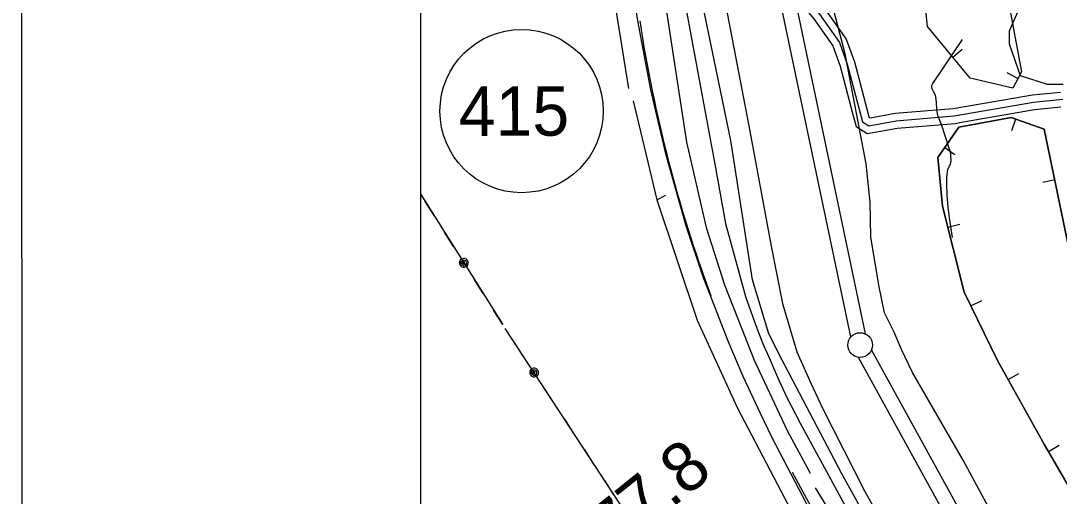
# Model space of a CAD drawing. Extents: x 3279314 to 3317160, y 734079 to 759431.
# Drawn here: x 3282648 to 3284746, y 754513 to 755474 of the extents above; entities that cross this region are included whole.
import ezdxf

# ---------------------------------------------------------------- set-up
doc = ezdxf.new("R2010")
doc.units = 0
for name, color, linetype in [('V-ANNO-SYMB', 7, 'Continuous'), ('V-BORW-LINE', 7, 'Continuous'), ('V-GRID-FRAM', 7, 'Continuous'), ('V-LEVE-TOET', 7, 'Continuous'), ('V-RAIL-TRAK', 7, 'Continuous'), ('V-ROAD-CNTR', 7, 'Continuous'), ('V-ROAD-IDEN', 7, 'Continuous'), ('V-SITE-VEGE', 7, 'Continuous'), ('V-SURV-IDEN', 7, 'Continuous'), ('V-SURV-LINE', 7, 'Continuous'), ('V-TOPO-SHOR', 7, 'Continuous'), ('V-UTIL-LINE', 7, 'Continuous')]:
    doc.layers.add(name, color=color, linetype=linetype)

msp = doc.modelspace()

# ---------------------------------------------------------------- linework, layer by layer
at = {"layer": 'V-ANNO-SYMB'}
msp.add_lwpolyline([(3282659.5, 735288.8), (3315742.7, 735305.7), (3315731, 758222.2), (3282647.8, 758205.4), (3282659.5, 735288.8)], dxfattribs=at)
at = {"layer": 'V-BORW-LINE'}
for p, q in [((3284530.4, 755400.2), (3284549.8, 755416)), ((3284662.3, 755356.9), (3284640.2, 755368.5)), ((3284657, 755274.9), (3284648.9, 755251.3)), ((3284514.4, 755217.2), (3284535, 755203.1)), ((3284736.7, 755152.1), (3284712.2, 755147)), ((3284520.5, 755056.6), (3284544.7, 755062.7)), ((3284566.9, 754897.2), (3284589.4, 754908.2)), ((3284642.3, 754748.7), (3284664.2, 754760.9)), ((3284723.6, 754603.3), (3284745.2, 754615.8))]:
    msp.add_line(p, q, dxfattribs=at)
for points in [[(3284443.5, 756381.2), (3284529.5, 756266.7), (3284588.4, 755977.5), (3284641.4, 755699.9), (3284641.7, 755519), (3284669.4, 755370.4), (3284651.9, 755337), (3284565.4, 755357.5), (3284479.7, 755462.1), (3284467.3, 755583.5), (3284485.3, 755733.9), (3284482.4, 755883.7), (3284433.7, 756025.3), (3284380.4, 756073.3), (3284306.3, 756131.2), (3284237.6, 756289.3), (3284261.2, 756356.9), (3284363.3, 756384.1), (3284401.4, 756388.1), (3284443.5, 756381.2)], [(3284814.7, 754445.9), (3284715.9, 754616.6), (3284621, 754786.9), (3284553.3, 754925), (3284510, 755098.6), (3284500.7, 755197.2), (3284542.7, 755258.5), (3284648.7, 755277.8), (3284715.5, 755254.7), (3284780.7, 754939.2), (3284907.5, 754719.2), (3285075.7, 754436.6)], [(3285075.7, 754436.6), (3284907.5, 754719.2), (3284780.7, 754939.2), (3284715.5, 755254.7), (3284648.7, 755277.8), (3284542.7, 755258.5), (3284500.7, 755197.2), (3284510, 755098.6), (3284553.3, 754925), (3284621, 754786.9), (3284715.9, 754616.6), (3284814.7, 754445.9)]]:
    msp.add_lwpolyline(points, dxfattribs=at)
at = {"layer": 'V-GRID-FRAM'}
msp.add_lwpolyline([(3283455.7, 757641.4), (3314923.7, 757657.4), (3314940.9, 739471.9), (3283457, 739455.9), (3283455.7, 757641.4)], dxfattribs=at)
at = {"layer": 'V-LEVE-TOET'}
for points in [[(3284644.5, 754412.7), (3284551.6, 754585.2), (3284449.4, 754762.4), (3284426.8, 754809.3), (3284411.7, 754845.8), (3284392.8, 754883.5), (3284381.3, 754939.2), (3284364.9, 755036.8), (3284363.7, 755106.6), (3284355.3, 755184.2), (3284312.9, 755406.5), (3284247.5, 755659.6), (3284190, 755952.8), (3284124.8, 756243.3), (3284085.2, 756438.3), (3284088.1, 756504.7), (3284084.8, 756539.5), (3284077.8, 756575.8), (3284068.5, 756624.9), (3284052.8, 756743), (3284027.8, 757013.7), (3284006.3, 757241.4), (3283980.1, 757578.9), (3283975, 757641.6)], [(3284068.6, 755521.1), (3284120.6, 755250.5), (3284163.4, 755017.7), (3284186.3, 754902.2), (3284215.5, 754804.1), (3284243.7, 754741.3), (3284267.8, 754689.5), (3284353, 754522.5), (3284441.6, 754364.8)]]:
    msp.add_lwpolyline(points, dxfattribs=at)
at = {"layer": 'V-RAIL-TRAK'}
msp.add_lwpolyline([(3284242.4, 754483.7), (3284166, 754630.4), (3284142.2, 754679.5), (3284106.8, 754754.9), (3284076.5, 754825.7), (3284026.6, 754956), (3283992.4, 755056.6), (3283951.4, 755202.1), (3283920.7, 755334), (3283894.4, 755473.1), (3283850.4, 755761.9), (3283810.2, 756041.6), (3283778.2, 756265.5), (3283736.2, 756545.8), (3283697, 756814.1), (3283643.5, 757184.1), (3283628.5, 757275.2), (3283616.3, 757343.9), (3283601.4, 757422.5), (3283565.5, 757579.5), (3283548.8, 757641.4)], dxfattribs=at)
at = {"layer": 'V-ROAD-CNTR'}
for points in [[(3283839.1, 756347.1), (3283944.2, 755754.6), (3284049.7, 755183.5), (3284071.3, 755063.7), (3284098.2, 754965.5), (3284111.9, 754916.5), (3284132.5, 754857.4), (3284146.1, 754822.8), (3284160.3, 754790.9), (3284176.2, 754753.3), (3284194.8, 754713.4), (3284222.4, 754660.3), (3284805.2, 753589.1), (3285080.3, 753080.2), (3285191.5, 752890.3)], [(3284193.9, 755568.2), (3284261.6, 755486.7), (3284302, 755429.6), (3284317.4, 755385.9), (3284348.2, 755269.5), (3284360.8, 755261.4), (3284416.4, 755271.6), (3284533.3, 755281.1), (3284693.8, 755308.8), (3284752.8, 755314.8)], [(3284193.9, 755568.2), (3284261.6, 755486.7), (3284302, 755429.6), (3284317.4, 755385.9), (3284348.2, 755269.5), (3284360.8, 755261.4), (3284416.4, 755271.6), (3284533.3, 755281.1), (3284693.8, 755308.8), (3284752.8, 755314.8)], [(3284205.4, 755577.8), (3284273.5, 755495.9), (3284315.4, 755436.5), (3284331.8, 755390.4), (3284357.6, 755292.7)], [(3284211.2, 755523.9), (3284249.7, 755477.6), (3284288.5, 755422.6), (3284303.1, 755381.5), (3284328.8, 755284.2)], [(3284554.7, 755300), (3284691.8, 755323.6), (3284748.5, 755329.4)], [(3284357.6, 755292.7), (3284361.2, 755279), (3284364, 755277.2), (3284414.5, 755286.5), (3284531.4, 755296), (3284554.7, 755300)], [(3284548.4, 755268.5), (3284695.8, 755293.9), (3284748.8, 755299.3)], [(3284328.8, 755284.2), (3284335.2, 755260), (3284357.7, 755245.6), (3284384.3, 755250.4)], [(3284384.3, 755250.4), (3284418.4, 755256.7), (3284535.2, 755266.2), (3284548.4, 755268.5)], [(3284205.8, 754561.4), (3284524.1, 753976.9), (3284835.6, 753402.6), (3285049.3, 753011.4), (3285136.3, 752849.5)]]:
    msp.add_lwpolyline(points, dxfattribs=at)
msp.add_arc((3286707.4, 755903.6), 2842, 188.7034, 200.2969, dxfattribs=at)
at = {"layer": 'V-ROAD-IDEN'}
msp.add_circle((3283659.6, 755291.1), 165, dxfattribs=at)
at = {"layer": 'V-SITE-VEGE'}
for p, q in [((3284644.9, 755453.3), (3284676.2, 755523.4)), ((3284644.9, 755426), (3284644.9, 755453.3)), ((3284667.6, 755362.5), (3284644.9, 755426)), ((3284722, 755344.4), (3284667.6, 755362.5)), ((3284753.7, 755344.4), (3284722, 755344.4))]:
    msp.add_line(p, q, dxfattribs=at)
at = {"layer": 'V-SURV-LINE'}
for points in [[(3284324.6, 754834.5), (3283981.8, 756466.9)], [(3284011.2, 756473.1), (3284353.9, 754840.7)], [(3284366.1, 754807.8), (3285301.4, 753107.7)], [(3285275.1, 753093.3), (3284339.8, 754793.3)]]:
    msp.add_lwpolyline(points, dxfattribs=at)
msp.add_circle((3284343.4, 754818.1), 25, dxfattribs=at)
at = {"layer": 'V-TOPO-SHOR'}
msp.add_line((3283837.7, 755571), (3283875.7, 755336.7), dxfattribs=at)
for points in [[(3284535.2, 754144), (3284305.6, 754559.3), (3284185.7, 754787.7), (3284159.1, 754840.7), (3284125.7, 754950), (3284081.9, 755231.7), (3283991.4, 755672.3)], [(3283935.2, 755602.6), (3283992.4, 755228.1), (3284032.6, 755055.9), (3284069.3, 754939.9), (3284129.4, 754787.6), (3284196, 754645.2), (3284242.6, 754559.1)], [(3284529.8, 755035.3), (3284523.9, 755075.2), (3284521.4, 755097), (3284519.3, 755121.9), (3284518.6, 755145.5), (3284518.7, 755156.5), (3284520.3, 755172.9), (3284523.1, 755178.9), (3284524.1, 755180.6), (3284525.7, 755183.9), (3284526.5, 755186.4), (3284527, 755189.5), (3284527, 755193.7), (3284526.9, 755197.4), (3284526.5, 755202.6), (3284526.4, 755203.7), (3284526.4, 755204.4), (3284524.8, 755211.7), (3284508.7, 755261.9), (3284500.2, 755282.1), (3284498.2, 755294.1), (3284497.4, 755308.9), (3284496.3, 755319.1), (3284495.4, 755322.9), (3284494.6, 755325.1), (3284493.3, 755327.3), (3284491.6, 755330.3), (3284489.3, 755334.3), (3284488.3, 755337.2), (3284488, 755338.5), (3284488.1, 755341.2), (3284488.4, 755342.8), (3284489, 755344), (3284489.7, 755345.6), (3284490.3, 755346.8), (3284550.3, 755435.6)], [(3283885.2, 755311.7), (3283932.5, 755111.9), (3283951.2, 755121.3)], [(3283932.5, 755111.9), (3284014.3, 754868.4), (3284096, 754690.5), (3284256, 754384.7), (3284425.5, 754066.4)], [(3284252.6, 754529.3), (3284315.9, 754426.7), (3284552.2, 753999.6)]]:
    msp.add_lwpolyline(points, dxfattribs=at)
at = {"layer": 'V-UTIL-LINE'}
for points in [[(3283455.9, 755122.4), (3283621.3, 754859.9)], [(3283482.7, 755079.9), (3283464.6, 755108.6)], [(3283522.1, 755017.3), (3283504, 755046)], [(3283542.9, 754984.3), (3283541.8, 754981.6), (3283544.1, 754982.1), (3283545.1, 754984.6), (3283543.2, 754986.9), (3283540.3, 754985.3), (3283539.1, 754980.7), (3283542.7, 754978.4), (3283547.4, 754979.8), (3283548.6, 754984.2), (3283547.1, 754988.4), (3283542.5, 754989.9), (3283537.7, 754987.3), (3283535.3, 754979.5), (3283537.7, 754976.9), (3283540.9, 754975.5), (3283544.4, 754975.4), (3283547.7, 754976.6), (3283550.3, 754979.1), (3283551.7, 754982.3), (3283551.8, 754985.8), (3283550.5, 754989.1), (3283548.1, 754991.6), (3283544.9, 754993), (3283541.4, 754993.1), (3283538.1, 754991.9), (3283535.6, 754989.5), (3283534.1, 754986.3), (3283534, 754982.7), (3283535.3, 754979.5)], [(3283581.8, 754922.5), (3283563.7, 754951.3)], [(3283621.3, 754859.9), (3283603.1, 754888.7)], [(3288738.4, 746569.3), (3288636.9, 747168.8), (3288472.7, 747753.3), (3288305, 748308.9), (3288066.2, 748903.2), (3287813.4, 749483), (3287572, 750013.5), (3287250.9, 750510.8), (3286873.5, 750937.9), (3286412.5, 751389.7), (3286105.8, 751626.1), (3285807.9, 751895.5), (3285494.3, 752160.6), (3284875.4, 752907.1), (3284538.1, 753405.9), (3283938.7, 754373.8), (3283626.5, 754851.9)], [(3283663.4, 754795.3), (3283644.8, 754823.8)], [(3283684.8, 754762.7), (3283683.7, 754760), (3283685.9, 754760.5), (3283686.9, 754763.1), (3283685, 754765.4), (3283682.1, 754763.6), (3283681, 754759.1), (3283684.7, 754756.8), (3283689.3, 754758.3), (3283690.4, 754762.7), (3283688.9, 754766.9), (3283684.3, 754768.3), (3283679.5, 754765.6), (3283677.2, 754757.8), (3283679.7, 754755.2), (3283682.9, 754753.9), (3283686.4, 754753.8), (3283689.7, 754755.1), (3283692.2, 754757.6), (3283693.6, 754760.8), (3283693.6, 754764.3), (3283692.3, 754767.6), (3283689.8, 754770.1), (3283686.6, 754771.5), (3283683.1, 754771.5), (3283679.8, 754770.2), (3283677.3, 754767.8), (3283675.9, 754764.5), (3283675.9, 754761), (3283677.2, 754757.8)], [(3283724.7, 754701.6), (3283706.1, 754730)], [(3283765.1, 754639.6), (3283746.6, 754668.1)], [(3283805.6, 754577.6), (3283787, 754606.1)], [(3283846.1, 754515.7), (3283827.5, 754544.2)]]:
    msp.add_lwpolyline(points, dxfattribs=at)

# ---------------------------------------------------------------- texts
at = {"layer": 'V-ROAD-IDEN'}
msp.add_text('415', height=100, rotation=0.1347, dxfattribs=at).set_placement((3283532.6, 755240.8))
at = {"layer": 'V-SURV-IDEN'}
msp.add_text('2900+77.8', height=100, rotation=38.7511, dxfattribs=at).set_placement((3283553.2, 754159))

doc.saveas('drawing.dxf')
